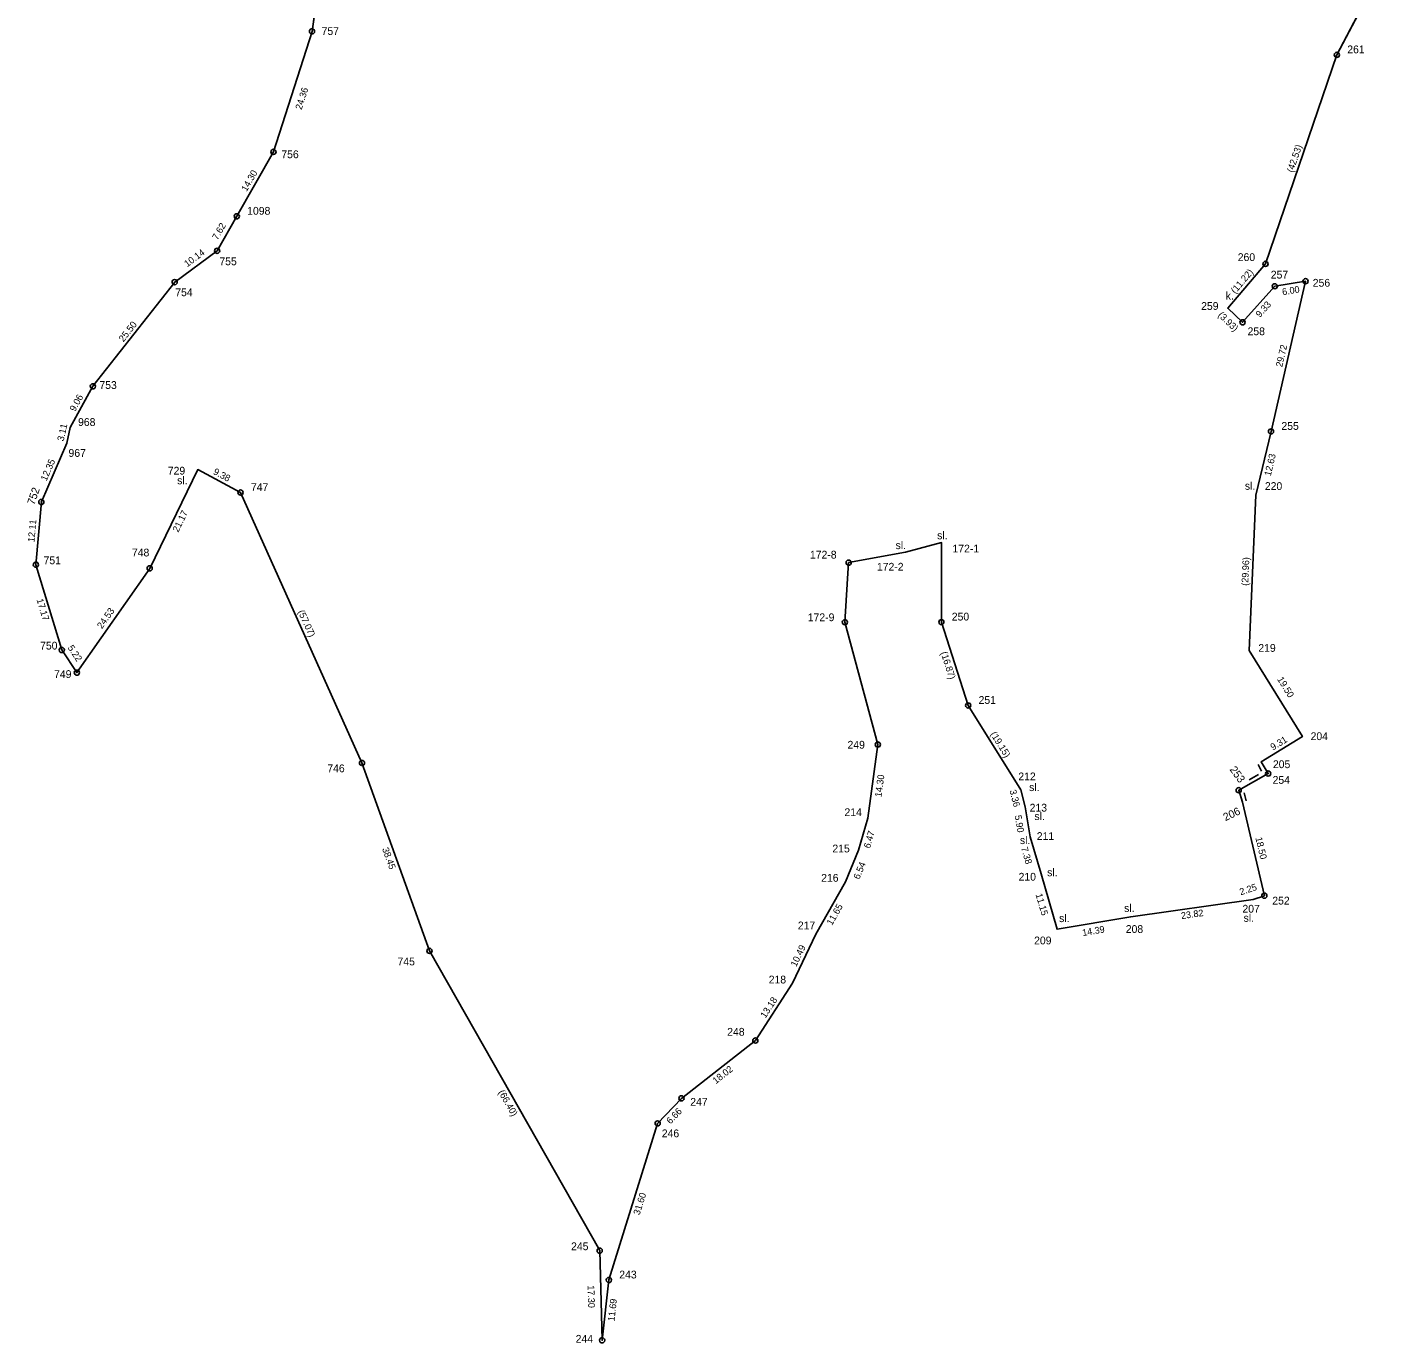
# Model space of a CAD drawing. Extents: x -555170 to -550532, y -1039598 to -1034701.
# Drawn here: x -552501.3 to -552240.6, y -1036038.5 to -1035785.1 of the extents above; entities that cross this region are included whole.
import ezdxf

# ---------------------------------------------------------------- set-up
doc = ezdxf.new("R2010")
doc.units = 0
for name, color, linetype in [('Vrstva 10', 7, 'Continuous'), ('Vrstva 40', 7, 'Continuous'), ('Vrstva 43', 7, 'Continuous'), ('Vrstva 48', 7, 'Continuous')]:
    doc.layers.add(name, color=color, linetype=linetype)

msp = doc.modelspace()

# ---------------------------------------------------------------- linework, layer by layer
at = {"layer": 'Vrstva 10'}
for p, q in [((-552264.25, -1035927.05), (-552263.61, -1035928.36)), ((-552264.19, -1035928.99), (-552266.01, -1035930.02)), ((-552266.96, -1035932.53), (-552266.57, -1035934.04))]:
    msp.add_line(p, q, dxfattribs=at)
at = {"layer": 'Vrstva 40'}
for p, q in [((-552441.77, -1035752.52), (-552446.42, -1035785.88)), ((-552249.09, -1035790.4), (-552240.61, -1035774.22)), ((-552446.42, -1035785.88), (-552453.85, -1035809.08)), ((-552262.82, -1035830.66), (-552249.09, -1035790.4)), ((-552453.85, -1035809.08), (-552460.91, -1035821.49)), ((-552460.91, -1035821.49), (-552464.7, -1035828.14)), ((-552464.7, -1035828.14), (-552472.86, -1035834.17)), ((-552270.11, -1035839.2), (-552262.82, -1035830.66)), ((-552472.86, -1035834.17), (-552488.61, -1035854.24)), ((-552261.77, -1035862.92), (-552255.13, -1035834)), ((-552255.13, -1035834), (-552261.05, -1035834.97)), ((-552261.05, -1035834.97), (-552267.26, -1035841.91)), ((-552267.26, -1035841.91), (-552270.11, -1035839.2)), ((-552488.61, -1035854.24), (-552492.98, -1035862.14)), ((-552492.98, -1035862.14), (-552493.65, -1035865.17)), ((-552264.68, -1035875.19), (-552261.77, -1035862.92)), ((-552493.65, -1035865.17), (-552498.54, -1035876.51)), ((-552477.68, -1035889.3), (-552468.44, -1035870.27)), ((-552468.44, -1035870.27), (-552460.18, -1035874.69)), ((-552460.18, -1035874.69), (-552436.81, -1035926.77)), ((-552265.96, -1035905.12), (-552264.68, -1035875.19)), ((-552498.54, -1035876.51), (-552499.6, -1035888.59)), ((-552343.1, -1035888.19), (-552332.15, -1035886.21)), ((-552332.15, -1035886.21), (-552325.21, -1035884.34)), ((-552325.21, -1035884.34), (-552325.24, -1035899.64)), ((-552499.6, -1035888.59), (-552494.6, -1035905.02)), ((-552343.82, -1035899.68), (-552343.1, -1035888.19)), ((-552491.7, -1035909.38), (-552477.68, -1035889.3)), ((-552337.48, -1035923.23), (-552343.82, -1035899.68)), ((-552325.24, -1035899.64), (-552320.08, -1035915.7)), ((-552494.6, -1035905.02), (-552491.7, -1035909.38)), ((-552255.72, -1035921.69), (-552265.96, -1035905.12)), ((-552320.08, -1035915.7), (-552309.93, -1035931.94)), ((-552263.67, -1035926.55), (-552255.72, -1035921.69)), ((-552339.41, -1035937.4), (-552337.48, -1035923.23)), ((-552436.81, -1035926.77), (-552423.81, -1035962.96)), ((-552262.32, -1035928.81), (-552263.67, -1035926.55)), ((-552268, -1035932.03), (-552262.32, -1035928.81)), ((-552309.93, -1035931.94), (-552309.11, -1035935.2)), ((-552267.29, -1035934.35), (-552268, -1035932.03)), ((-552309.11, -1035935.2), (-552308.13, -1035941.03)), ((-552263.06, -1035952.34), (-552267.29, -1035934.35)), ((-552341.21, -1035943.6), (-552339.41, -1035937.4)), ((-552308.13, -1035941.03), (-552306.06, -1035948.11)), ((-552343.7, -1035949.65), (-552341.21, -1035943.6)), ((-552306.06, -1035948.11), (-552302.97, -1035958.8)), ((-552349.41, -1035959.74), (-552343.7, -1035949.65)), ((-552288.79, -1035956.4), (-552265.21, -1035953.05)), ((-552265.21, -1035953.05), (-552263.06, -1035952.34)), ((-552302.97, -1035958.8), (-552288.79, -1035956.4)), ((-552353.93, -1035969.21), (-552349.41, -1035959.74)), ((-552423.81, -1035962.96), (-552391.03, -1036020.7)), ((-552361.06, -1035980.24), (-552353.93, -1035969.21)), ((-552375.3, -1035991.37), (-552361.06, -1035980.24)), ((-552379.88, -1035996.19), (-552375.3, -1035991.37)), ((-552389.26, -1036026.35), (-552379.88, -1035996.19)), ((-552391.03, -1036020.7), (-552390.56, -1036037.97)), ((-552390.56, -1036037.97), (-552389.26, -1036026.35))]:
    msp.add_line(p, q, dxfattribs=at)
at = {"layer": 'Vrstva 43'}
for p, q in [((-552446.42, -1035785.88), (-552446.42, -1035785.88)), ((-552249.09, -1035790.4), (-552249.09, -1035790.4)), ((-552453.85, -1035809.08), (-552453.85, -1035809.08)), ((-552460.91, -1035821.49), (-552460.91, -1035821.49)), ((-552464.7, -1035828.14), (-552464.7, -1035828.14)), ((-552262.82, -1035830.66), (-552262.82, -1035830.66)), ((-552472.86, -1035834.17), (-552472.86, -1035834.17)), ((-552255.13, -1035834), (-552255.13, -1035834)), ((-552261.05, -1035834.97), (-552261.05, -1035834.97)), ((-552270.11, -1035839.2), (-552270.11, -1035839.2)), ((-552267.26, -1035841.91), (-552267.26, -1035841.91)), ((-552488.61, -1035854.24), (-552488.61, -1035854.24)), ((-552492.98, -1035862.14), (-552492.98, -1035862.14)), ((-552261.77, -1035862.92), (-552261.77, -1035862.92)), ((-552493.65, -1035865.17), (-552493.65, -1035865.17)), ((-552468.44, -1035870.27), (-552468.44, -1035870.27)), ((-552460.18, -1035874.69), (-552460.18, -1035874.69)), ((-552264.68, -1035875.19), (-552264.68, -1035875.19)), ((-552498.54, -1035876.51), (-552498.54, -1035876.51)), ((-552332.15, -1035886.21), (-552332.15, -1035886.21)), ((-552325.21, -1035884.34), (-552325.21, -1035884.34)), ((-552499.6, -1035888.59), (-552499.6, -1035888.59)), ((-552343.1, -1035888.19), (-552343.1, -1035888.19)), ((-552477.68, -1035889.3), (-552477.68, -1035889.3)), ((-552343.82, -1035899.68), (-552343.82, -1035899.68)), ((-552325.24, -1035899.64), (-552325.24, -1035899.64)), ((-552494.6, -1035905.02), (-552494.6, -1035905.02)), ((-552265.96, -1035905.12), (-552265.96, -1035905.12)), ((-552491.7, -1035909.38), (-552491.7, -1035909.38)), ((-552320.08, -1035915.7), (-552320.08, -1035915.7)), ((-552255.72, -1035921.69), (-552255.72, -1035921.69)), ((-552337.48, -1035923.23), (-552337.48, -1035923.23)), ((-552436.81, -1035926.77), (-552436.81, -1035926.77)), ((-552263.67, -1035926.55), (-552263.67, -1035926.55)), ((-552262.32, -1035928.81), (-552262.32, -1035928.81)), ((-552309.93, -1035931.94), (-552309.93, -1035931.94)), ((-552268, -1035932.03), (-552268, -1035932.03)), ((-552309.11, -1035935.2), (-552309.11, -1035935.2)), ((-552267.29, -1035934.35), (-552267.29, -1035934.35)), ((-552339.41, -1035937.4), (-552339.41, -1035937.4)), ((-552308.13, -1035941.03), (-552308.13, -1035941.03)), ((-552341.21, -1035943.6), (-552341.21, -1035943.6)), ((-552306.06, -1035948.11), (-552306.06, -1035948.11)), ((-552343.7, -1035949.65), (-552343.7, -1035949.65)), ((-552265.21, -1035953.05), (-552265.21, -1035953.05)), ((-552263.06, -1035952.34), (-552263.06, -1035952.34)), ((-552288.79, -1035956.4), (-552288.79, -1035956.4)), ((-552302.97, -1035958.8), (-552302.97, -1035958.8)), ((-552349.41, -1035959.74), (-552349.41, -1035959.74)), ((-552423.81, -1035962.96), (-552423.81, -1035962.96)), ((-552353.93, -1035969.21), (-552353.93, -1035969.21)), ((-552361.06, -1035980.24), (-552361.06, -1035980.24)), ((-552375.3, -1035991.37), (-552375.3, -1035991.37)), ((-552379.88, -1035996.19), (-552379.88, -1035996.19)), ((-552391.03, -1036020.7), (-552391.03, -1036020.7)), ((-552389.26, -1036026.35), (-552389.26, -1036026.35)), ((-552390.56, -1036037.97), (-552390.56, -1036037.97))]:
    msp.add_line(p, q, dxfattribs=at)
for centre, radius in [((-552446.42, -1035785.88), 0.5), ((-552446.42, -1035785.88), 0.01), ((-552249.09, -1035790.4), 0.5), ((-552249.09, -1035790.4), 0.01), ((-552453.85, -1035809.08), 0.5), ((-552453.85, -1035809.08), 0.01), ((-552460.91, -1035821.49), 0.5), ((-552460.91, -1035821.49), 0.01), ((-552464.7, -1035828.14), 0.5), ((-552464.7, -1035828.14), 0.01), ((-552262.82, -1035830.66), 0.5), ((-552262.82, -1035830.66), 0.01), ((-552472.87, -1035834.17), 0.5), ((-552472.87, -1035834.17), 0.01), ((-552255.13, -1035834), 0.5), ((-552255.13, -1035834), 0.01), ((-552261.05, -1035834.97), 0.5), ((-552261.05, -1035834.97), 0.01), ((-552267.26, -1035841.91), 0.5), ((-552267.26, -1035841.91), 0.01), ((-552488.61, -1035854.24), 0.5), ((-552488.61, -1035854.24), 0.01), ((-552261.77, -1035862.92), 0.5), ((-552261.77, -1035862.92), 0.01), ((-552498.54, -1035876.51), 0.5), ((-552460.18, -1035874.69), 0.5), ((-552460.18, -1035874.69), 0.01), ((-552498.54, -1035876.51), 0.01), ((-552499.6, -1035888.59), 0.5), ((-552499.6, -1035888.59), 0.01), ((-552477.68, -1035889.3), 0.5), ((-552343.1, -1035888.19), 0.5), ((-552343.1, -1035888.19), 0.01), ((-552477.68, -1035889.3), 0.01), ((-552343.82, -1035899.68), 0.5), ((-552325.24, -1035899.64), 0.5), ((-552343.82, -1035899.68), 0.01), ((-552325.24, -1035899.64), 0.01), ((-552494.6, -1035905.02), 0.5), ((-552494.6, -1035905.02), 0.01), ((-552491.7, -1035909.38), 0.5), ((-552491.7, -1035909.38), 0.01), ((-552320.08, -1035915.7), 0.5), ((-552320.08, -1035915.7), 0.01), ((-552337.48, -1035923.23), 0.5), ((-552337.48, -1035923.23), 0.01), ((-552436.81, -1035926.77), 0.5), ((-552436.81, -1035926.77), 0.01), ((-552262.32, -1035928.81), 0.5), ((-552262.32, -1035928.81), 0.01), ((-552268, -1035932.03), 0.5), ((-552268, -1035932.03), 0.01), ((-552263.06, -1035952.34), 0.5), ((-552263.06, -1035952.34), 0.01), ((-552423.81, -1035962.96), 0.5), ((-552423.81, -1035962.96), 0.01), ((-552361.06, -1035980.24), 0.5), ((-552361.06, -1035980.24), 0.01), ((-552375.3, -1035991.37), 0.5), ((-552375.3, -1035991.37), 0.01), ((-552379.88, -1035996.19), 0.5), ((-552379.88, -1035996.19), 0.01), ((-552391.03, -1036020.7), 0.5), ((-552391.03, -1036020.7), 0.01), ((-552389.26, -1036026.35), 0.5), ((-552389.26, -1036026.35), 0.01), ((-552390.56, -1036037.97), 0.5), ((-552390.56, -1036037.97), 0.01)]:
    msp.add_circle(centre, radius, dxfattribs=at)
at = {"layer": 'Vrstva 48'}
msp.add_lwpolyline([(-552240.61, -1035774.22), (-552249.09, -1035790.4), (-552262.82, -1035830.66), (-552270.11, -1035839.2), (-552267.26, -1035841.91), (-552261.05, -1035834.97), (-552255.13, -1035834), (-552261.77, -1035862.92), (-552264.68, -1035875.19), (-552265.96, -1035905.12), (-552255.72, -1035921.69), (-552263.67, -1035926.55), (-552262.32, -1035928.81), (-552268, -1035932.03), (-552267.29, -1035934.35), (-552263.06, -1035952.34), (-552265.21, -1035953.05), (-552288.79, -1035956.4), (-552302.97, -1035958.8), (-552306.06, -1035948.11), (-552308.13, -1035941.03), (-552309.11, -1035935.2), (-552309.93, -1035931.94), (-552320.08, -1035915.7), (-552325.24, -1035899.64), (-552325.21, -1035884.34), (-552332.15, -1035886.21), (-552343.1, -1035888.19), (-552343.82, -1035899.68), (-552337.48, -1035923.23), (-552339.41, -1035937.4), (-552341.21, -1035943.6), (-552343.7, -1035949.65), (-552349.41, -1035959.74), (-552353.93, -1035969.21), (-552361.06, -1035980.24), (-552375.3, -1035991.37), (-552379.88, -1035996.19), (-552389.26, -1036026.35), (-552390.56, -1036037.97), (-552391.03, -1036020.7), (-552423.81, -1035962.96), (-552436.81, -1035926.77), (-552460.18, -1035874.69), (-552468.44, -1035870.27), (-552477.68, -1035889.3), (-552491.7, -1035909.38), (-552494.6, -1035905.02), (-552499.6, -1035888.59), (-552498.54, -1035876.51), (-552493.65, -1035865.17), (-552492.98, -1035862.14), (-552488.61, -1035854.24), (-552472.86, -1035834.17), (-552464.7, -1035828.14), (-552460.91, -1035821.49), (-552453.85, -1035809.08), (-552446.42, -1035785.88), (-552441.77, -1035752.52)], dxfattribs=at)

# ---------------------------------------------------------------- texts
at = {"layer": 'Vrstva 10'}
for s, rotation, p in [('24.36', 72.2341, (-552448.44, -1035801.08)), ('(42.53)', 71.1664, (-552257.54, -1035813.17)), ('14.30', 60.3656, (-552459.02, -1035816.84)), ('7.62', 60.3656, (-552464.61, -1035826.17)), ('10.14', 36.4126, (-552470.45, -1035831.33)), ('(11.22)', 49.5181, (-552268.66, -1035836.5)), ('6.00', 9.3099, (-552259.53, -1035836.7)), ('9.33', 48.1902, (-552263.9, -1035841.08)), ('25.50', 51.8808, (-552482.73, -1035845.79)), ('(3.93)', 316.3322, (-552272.1, -1035840.66)), ('29.72', 77.0662, (-552259.62, -1035850.62)), ('9.06', 61.0721, (-552492.05, -1035859.21)), ('3.11', 77.5313, (-552494.25, -1035864.89)), ('12.63', 76.6742, (-552261.83, -1035871.61)), ('12.35', 66.6929, (-552497.55, -1035872.59)), ('9.38', 331.8577, (-552465.57, -1035871.07)), ('21.17', 64.1079, (-552472.18, -1035882.44)), ('12.11', 84.9723, (-552499.87, -1035884.28)), ('(29.96)', 87.5512, (-552266.17, -1035892.67)), ('17.17', 286.9184, (-552499.48, -1035895.34)), ('24.53', 55.0632, (-552486.87, -1035901.04)), ('(57.07)', 294.1635, (-552449.17, -1035897.65)), ('5.22', 303.6356, (-552493.54, -1035904.59)), ('(16.87)', 287.808, (-552325.39, -1035905.55)), ('19.50', 301.7154, (-552260.64, -1035910.65)), ('(19.15)', 302.0075, (-552315.86, -1035921.22)), ('9.31', 31.4383, (-552261.4, -1035924.4)), ('14.30', 82.2439, (-552336.79, -1035933.41)), ('3.36', 284.1189, (-552312.13, -1035932.09)), ('5.90', 279.542, (-552311.13, -1035936.93)), ('6.47', 73.8108, (-552339, -1035943.32)), ('18.50', 283.2261, (-552264.8, -1035941.2)), ('38.45', 289.7615, (-552432.94, -1035943.31)), ('7.38', 286.2975, (-552309.93, -1035943.16)), ('6.54', 67.6294, (-552341.05, -1035949.3)), ('2.25', 18.1879, (-552267.59, -1035952.26)), ('11.65', 60.4942, (-552346.3, -1035958.16)), ('11.15', 286.1222, (-552307.12, -1035952.1)), ('23.82', 8.0859, (-552279.01, -1035956.86)), ('14.39', 9.6064, (-552298.01, -1035960.12)), ('10.49', 64.485, (-552353.19, -1035966.14)), ('13.18', 57.1023, (-552359.12, -1035976.03)), ('18.02', 38.021, (-552368.67, -1035988.66)), ('(66.40)', 299.5838, (-552410.6, -1035990.18)), ('6.66', 46.4922, (-552377.41, -1035996.42)), ('31.60', 72.7212, (-552383.35, -1036013.93)), ('17.30', 271.5589, (-552393.36, -1036027.39)), ('11.69', 83.6165, (-552388.19, -1036034.36))]:
    msp.add_text(s, height=1.3, rotation=rotation, dxfattribs=at).set_placement(p)
at = {"layer": 'Vrstva 43'}
for s, p in [('757', (-552444.58, -1035786.57)), ('261', (-552247.09, -1035790.1)), ('756', (-552452.33, -1035810.3)), ('1098', (-552458.91, -1035821.19)), ('260', (-552268.18, -1035830.11)), ('755', (-552464.26, -1035830.92)), ('257', (-552261.82, -1035833.48)), ('256', (-552253.74, -1035835.05)), ('754', (-552472.75, -1035836.88)), ('k.', (-552270.5, -1035837.54)), ('259', (-552275.23, -1035839.52)), ('258', (-552266.29, -1035844.39)), ('753', (-552487.36, -1035854.74)), ('968', (-552491.47, -1035861.87)), ('255', (-552259.77, -1035862.62)), ('967', (-552493.31, -1035867.82)), ('729', (-552474.19, -1035871.24)), ('sl.', (-552472.39, -1035873.1)), ('747', (-552458.18, -1035874.39)), ('sl.', (-552266.81, -1035874.16)), ('220', (-552262.96, -1035874.2)), ('sl.', (-552326.06, -1035883.69)), ('748', (-552481.1, -1035887)), ('172-8', (-552350.55, -1035887.41)), ('sl.', (-552334.06, -1035885.59)), ('172-1', (-552323.11, -1035886.24)), ('751', (-552498.11, -1035888.5)), ('172-2', (-552337.66, -1035889.74)), ('172-9', (-552350.97, -1035899.47)), ('250', (-552323.24, -1035899.34)), ('750', (-552498.78, -1035904.93)), ('219', (-552264.22, -1035905.37)), ('749', (-552496.09, -1035910.41)), ('251', (-552318.08, -1035915.4)), ('249', (-552343.32, -1035924.02)), ('204', (-552254.15, -1035922.37)), ('746', (-552443.48, -1035928.56)), ('205', (-552261.41, -1035927.77)), ('212', (-552310.43, -1035930.12)), ('sl.', (-552308.35, -1035932.19)), ('254', (-552261.47, -1035930.79)), ('214', (-552343.9, -1035937.01)), ('213', (-552308.25, -1035936.14)), ('sl.', (-552307.34, -1035937.77)), ('sl.', (-552310.12, -1035942.4)), ('211', (-552306.88, -1035941.61)), ('215', (-552346.23, -1035944)), ('216', (-552348.39, -1035949.65)), ('210', (-552310.38, -1035949.44)), ('sl.', (-552304.88, -1035948.59)), ('sl.', (-552290.06, -1035955.48)), ('207', (-552267.28, -1035955.6)), ('252', (-552261.53, -1035954.04)), ('sl.', (-552302.58, -1035957.42)), ('sl.', (-552267.05, -1035957.36)), ('217', (-552352.88, -1035958.82)), ('208', (-552289.74, -1035959.51)), ('209', (-552307.39, -1035961.71)), ('745', (-552429.96, -1035965.76)), ('218', (-552358.49, -1035969.24)), ('248', (-552366.48, -1035979.3)), ('247', (-552373.59, -1035992.79)), ('246', (-552379.08, -1035998.86)), ('245', (-552396.54, -1036020.61)), ('243', (-552387.26, -1036026.05)), ('244', (-552395.66, -1036038.43))]:
    msp.add_text(s, height=1.5, dxfattribs=at).set_placement(p)
for s, rotation, p in [('752', 71.1, (-552499.9, -1035877.19)), ('253', 306, (-552269.82, -1035928.05)), ('206', 25.2, (-552270.56, -1035938))]:
    msp.add_text(s, height=1.5, rotation=rotation, dxfattribs=at).set_placement(p)

doc.saveas('drawing.dxf')
